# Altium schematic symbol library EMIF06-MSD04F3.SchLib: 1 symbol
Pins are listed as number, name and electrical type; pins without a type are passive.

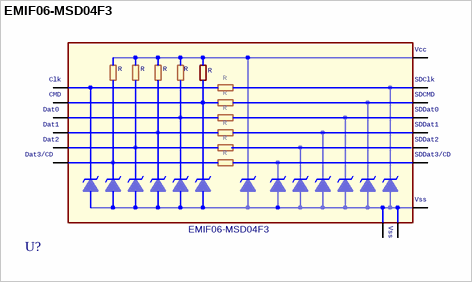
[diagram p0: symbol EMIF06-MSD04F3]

## EMIF06-MSD04F3
designator U?
footprint ST_CSP16N40P4X4_154X154X61
pins: A1 Dat0, A2 Dat1, A3 SDDat1, A4 SDDat0, B1 Clk, B2 Vcc, B3 Vss2, B4 SDClk, C1 CMD, C2 Vss, C3 Vss1, C4 SDCMD, D1 Dat3/CD, D2 Dat2, D3 SDDat2, D4 SDDat3/CD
